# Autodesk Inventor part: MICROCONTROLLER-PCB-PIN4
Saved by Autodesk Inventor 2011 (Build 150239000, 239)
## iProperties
Created: 2010-06
Part Number: MICROCONTROLLER-PCB-PIN4
Document SubType Name: Modeling
Designer: kurdi
Density: 1 g/cm^3
Author: kurdi
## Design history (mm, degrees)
feature "Base1"
node "NONE"
